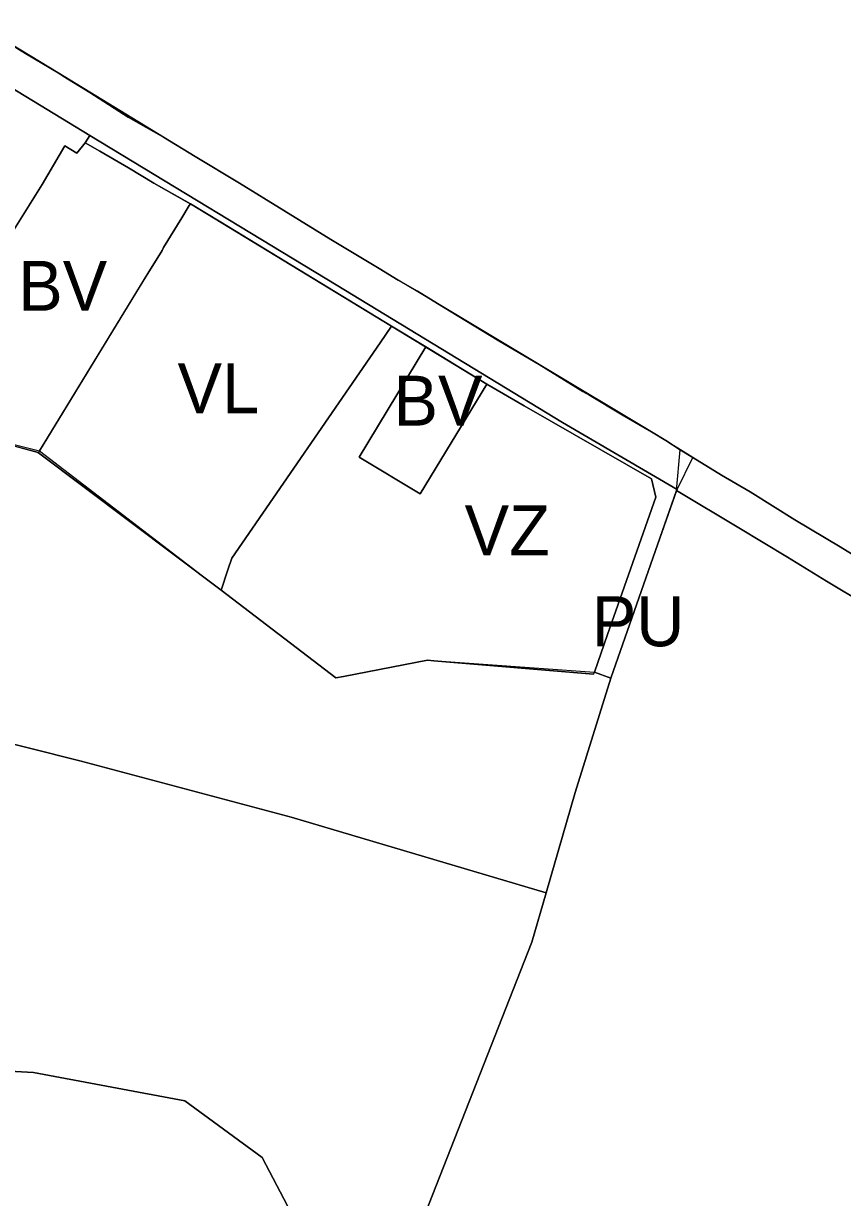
# Model space of a CAD drawing. Extents: x -555509 to -553005, y -1186756 to -1182560.
# Drawn here: x -553829.3 to -553599.5, y -1185808.2 to -1185478.8 of the extents above; entities that cross this region are included whole.
import ezdxf

# ---------------------------------------------------------------- set-up
doc = ezdxf.new("R2010")
doc.units = 0
for name, color, linetype in [('Level 15', 7, 'Continuous'), ('Level 36', 7, 'Continuous'), ('Level 52', 7, 'Continuous'), ('Level 59', 7, 'Continuous'), ('Level 6', 7, 'Continuous'), ('Level 63', 7, 'Continuous'), ('OBRYS_PLOCH', 7, 'Continuous'), ('stav_AL', 7, 'Continuous'), ('stav_AP', 7, 'Continuous'), ('stav_BV', 7, 'Continuous'), ('stav_DS', 7, 'Continuous'), ('stav_OS', 7, 'Continuous'), ('stav_PU', 7, 'Continuous'), ('stav_VL', 7, 'Continuous'), ('stav_VZ', 7, 'Continuous'), ('stav_ZK', 7, 'Continuous')]:
    doc.layers.add(name, color=color, linetype=linetype)

msp = doc.modelspace()

# ---------------------------------------------------------------- linework, layer by layer
at = {"layer": 'Level 15'}
for p, q in [((-553741.55, -1185552.19), (-553810.71, -1185510.27)), ((-553807.93, -1185514.67), (-553799.85, -1185519.34)), ((-553792.76, -1185523.64), (-553783.02, -1185529.12)), ((-553783.02, -1185529.12), (-553782.49, -1185529.43)), ((-553678.06, -1185590.77), (-553741.55, -1185552.19)), ((-553688.82, -1185586.12), (-553653.09, -1185606.6)), ((-553645.88, -1185609.63), (-553678.06, -1185590.77)), ((-553646.02, -1185609.88), (-553645.88, -1185609.63)), ((-553665.39, -1185650.28), (-553669.09, -1185660.85)), ((-553669.09, -1185660.85), (-553664.47, -1185662.51))]:
    msp.add_line(p, q, dxfattribs=at)
for points in [[(-553810.71, -1185510.27), (-553811.98, -1185512.28)], [(-553811.98, -1185512.28), (-553807.93, -1185514.67)], [(-553799.85, -1185519.34), (-553792.76, -1185523.64)], [(-553782.49, -1185529.43), (-553726.01, -1185563.76), (-553699.25, -1185580.02)], [(-553699.25, -1185580.02), (-553688.82, -1185586.12)], [(-553653.09, -1185606.6), (-553651.88, -1185611.74), (-553665.39, -1185650.28)], [(-553664.47, -1185662.51), (-553646.02, -1185609.88)]]:
    msp.add_lwpolyline(points, dxfattribs=at)
at = {"layer": 'Level 36'}
msp.add_lwpolyline([(-553842.47, -1185594.31), (-553824.8, -1185598.76), (-553773.82, -1185637.86), (-553741.7, -1185662.44), (-553715.92, -1185657.49), (-553669.09, -1185660.85), (-553664.47, -1185662.51), (-553645.88, -1185609.63), (-553641.45, -1185600.6), (-553653.09, -1185593.45), (-553684.56, -1185574.48), (-553713.17, -1185557.43), (-553724.17, -1185550.89), (-553743.1, -1185539.42), (-553756.23, -1185531.27), (-553768.7, -1185523.6), (-553781.13, -1185516.16), (-553790.01, -1185510.75), (-553819.6, -1185492.7), (-553841.14, -1185479.67)], dxfattribs=at)
at = {"layer": 'Level 52'}
for points in [[(-553669.37, -1185661.4), (-553669.09, -1185660.85), (-553664.47, -1185662.51), (-553646.02, -1185609.88), (-553645.05, -1185598.5), (-553649.07, -1185595.88), (-553653.09, -1185593.45), (-553661.34, -1185588.67), (-553670.5, -1185583.12), (-553672.3, -1185582.14), (-553684.56, -1185574.48), (-553695.87, -1185567.84), (-553707.58, -1185560.78), (-553713.17, -1185557.43), (-553718.78, -1185553.92), (-553724.17, -1185550.89), (-553729.53, -1185547.56), (-553736.09, -1185543.66), (-553743.1, -1185539.42), (-553756.23, -1185531.27), (-553768.7, -1185523.6), (-553781.13, -1185516.16), (-553790.01, -1185510.75), (-553799.92, -1185505.11), (-553810.66, -1185498.16), (-553818.19, -1185493.66), (-553819.6, -1185492.7), (-553828.72, -1185487.23), (-553841.14, -1185479.67)], [(-553840.96, -1185594.97), (-553825.6, -1185598.98), (-553825.09, -1185599.26), (-553773.82, -1185637.86), (-553741.7, -1185662.44), (-553739.47, -1185662.06), (-553715.92, -1185657.49), (-553714.12, -1185657.64), (-553669.37, -1185661.4)]]:
    msp.add_lwpolyline(points, dxfattribs=at)
at = {"layer": 'Level 6'}
for points in [[(-553669.37, -1185661.4), (-553669.09, -1185660.85), (-553664.47, -1185662.51), (-553646.02, -1185609.88), (-553645.05, -1185598.5), (-553649.07, -1185595.88), (-553653.09, -1185593.45), (-553661.34, -1185588.67), (-553670.5, -1185583.12), (-553672.3, -1185582.14), (-553684.56, -1185574.48), (-553695.87, -1185567.84), (-553707.58, -1185560.78), (-553713.17, -1185557.43), (-553718.78, -1185553.92), (-553724.17, -1185550.89), (-553729.53, -1185547.56), (-553736.09, -1185543.66), (-553743.1, -1185539.42), (-553756.23, -1185531.27), (-553768.7, -1185523.6), (-553781.13, -1185516.16), (-553790.01, -1185510.75), (-553799.92, -1185505.11), (-553810.66, -1185498.16), (-553818.19, -1185493.66), (-553819.6, -1185492.7), (-553828.72, -1185487.23), (-553841.14, -1185479.67)], [(-553840.96, -1185594.97), (-553825.6, -1185598.98), (-553825.09, -1185599.26), (-553773.82, -1185637.86), (-553741.7, -1185662.44), (-553739.47, -1185662.06), (-553715.92, -1185657.49), (-553714.12, -1185657.64), (-553669.37, -1185661.4)]]:
    msp.add_lwpolyline(points, dxfattribs=at)
at = {"layer": 'OBRYS_PLOCH'}
for p, q in [((-553810.71, -1185510.27), (-553811.98, -1185512.28)), ((-553741.55, -1185552.19), (-553810.71, -1185510.27)), ((-553810.71, -1185510.27), (-553741.55, -1185552.19)), ((-553811.98, -1185512.28), (-553807.93, -1185514.67)), ((-553807.93, -1185514.67), (-553811.98, -1185512.28)), ((-553807.93, -1185514.67), (-553799.85, -1185519.34)), ((-553799.85, -1185519.34), (-553807.93, -1185514.67)), ((-553768.7, -1185523.6), (-553781.13, -1185516.16)), ((-553799.85, -1185519.34), (-553792.76, -1185523.64)), ((-553792.76, -1185523.64), (-553799.85, -1185519.34)), ((-553792.76, -1185523.64), (-553783.02, -1185529.12)), ((-553782.49, -1185529.43), (-553792.76, -1185523.64)), ((-553782.81, -1185529.95), (-553784.83, -1185533.39)), ((-553784.83, -1185533.39), (-553782.81, -1185529.95)), ((-553783.02, -1185529.12), (-553782.49, -1185529.43)), ((-553782.49, -1185529.43), (-553782.81, -1185529.95)), ((-553782.81, -1185529.95), (-553782.49, -1185529.43)), ((-553773.94, -1185534.62), (-553782.49, -1185529.43)), ((-553784.83, -1185533.39), (-553789.98, -1185541.71)), ((-553726.01, -1185563.76), (-553773.94, -1185534.62)), ((-553789.98, -1185541.71), (-553790.41, -1185542.52)), ((-553736.09, -1185543.66), (-553743.1, -1185539.42)), ((-553790.41, -1185542.52), (-553794.42, -1185548.98)), ((-553729.53, -1185547.56), (-553736.09, -1185543.66)), ((-553724.17, -1185550.89), (-553729.53, -1185547.56)), ((-553795.51, -1185550.77), (-553824.8, -1185598.76)), ((-553794.42, -1185548.98), (-553795.51, -1185550.77)), ((-553718.78, -1185553.92), (-553724.17, -1185550.89)), ((-553678.06, -1185590.77), (-553741.55, -1185552.19)), ((-553741.55, -1185552.19), (-553678.06, -1185590.77)), ((-553713.17, -1185557.43), (-553718.78, -1185553.92)), ((-553707.58, -1185560.78), (-553713.17, -1185557.43)), ((-553729.23, -1185568.43), (-553726.01, -1185563.76)), ((-553770.83, -1185628.82), (-553729.23, -1185568.43)), ((-553716.43, -1185569.58), (-553735.08, -1185600.53)), ((-553699.25, -1185580.02), (-553716.43, -1185569.58)), ((-553672.3, -1185582.14), (-553684.56, -1185574.48)), ((-553699.25, -1185580.02), (-553688.82, -1185586.12)), ((-553670.5, -1185583.12), (-553672.3, -1185582.14)), ((-553661.34, -1185588.67), (-553670.5, -1185583.12)), ((-553653.09, -1185606.6), (-553688.82, -1185586.12)), ((-553688.82, -1185586.12), (-553653.09, -1185606.6)), ((-553645.88, -1185609.63), (-553678.06, -1185590.77)), ((-553678.06, -1185590.77), (-553645.88, -1185609.63)), ((-553645.05, -1185598.5), (-553649.07, -1185595.88)), ((-553824.8, -1185598.76), (-553825.09, -1185599.26)), ((-553825.09, -1185599.26), (-553773.82, -1185637.86)), ((-553641.45, -1185600.6), (-553645.05, -1185598.5)), ((-553664.47, -1185662.51), (-553646.02, -1185609.88)), ((-553646.02, -1185609.88), (-553664.47, -1185662.51)), ((-553646.02, -1185609.88), (-553664.47, -1185662.51)), ((-553646.02, -1185609.88), (-553645.88, -1185609.63)), ((-553645.88, -1185609.63), (-553646.02, -1185609.88)), ((-553646.02, -1185609.88), (-553628.57, -1185620.34)), ((-553628.57, -1185620.34), (-553646.02, -1185609.88)), ((-553628.57, -1185620.34), (-553646.02, -1185609.88)), ((-553628.57, -1185620.34), (-553614.92, -1185628.59)), ((-553614.92, -1185628.59), (-553628.57, -1185620.34)), ((-553614.92, -1185628.59), (-553628.57, -1185620.34)), ((-553771.93, -1185632.13), (-553770.83, -1185628.82)), ((-553603.99, -1185635.31), (-553614.92, -1185628.59)), ((-553773.82, -1185637.86), (-553771.93, -1185632.13)), ((-553592.98, -1185641.81), (-553603.99, -1185635.31)), ((-553665.39, -1185650.28), (-553669.09, -1185660.85)), ((-553715.92, -1185657.49), (-553739.47, -1185662.06)), ((-553674.53, -1185694.64), (-553664.47, -1185662.51)), ((-553664.47, -1185662.51), (-553674.53, -1185694.64)), ((-553664.47, -1185662.51), (-553674.53, -1185694.64)), ((-553664.47, -1185662.51), (-553669.09, -1185660.85)), ((-553669.09, -1185660.85), (-553664.47, -1185662.51)), ((-553754.19, -1185701.48), (-553813.14, -1185685.81)), ((-553674.53, -1185694.64), (-553682.62, -1185722.72)), ((-553674.53, -1185694.64), (-553682.62, -1185722.72)), ((-553682.62, -1185722.72), (-553754.19, -1185701.48)), ((-553682.62, -1185722.72), (-553686.62, -1185736.59)), ((-553682.62, -1185722.72), (-553686.62, -1185736.59)), ((-553686.62, -1185736.59), (-553682.62, -1185722.72)), ((-553686.62, -1185736.59), (-553735.32, -1185860.26)), ((-553686.62, -1185736.59), (-553735.32, -1185860.26)), ((-553735.32, -1185860.26), (-553686.62, -1185736.59)), ((-553826.51, -1185773.19), (-553784.01, -1185781.14))]:
    msp.add_line(p, q, dxfattribs=at)
for points in [[(-553811.98, -1185512.28), (-553810.71, -1185510.27), (-553822.69, -1185503.01), (-553895.23, -1185458.75), (-553919.14, -1185443.31)], [(-553895.23, -1185458.75), (-553822.69, -1185503.01), (-553810.71, -1185510.27)], [(-553841.14, -1185479.67), (-553828.72, -1185487.23), (-553819.6, -1185492.7), (-553818.19, -1185493.66), (-553810.66, -1185498.16), (-553799.92, -1185505.11), (-553790.01, -1185510.75), (-553781.13, -1185516.16), (-553768.7, -1185523.6), (-553756.23, -1185531.27), (-553743.1, -1185539.42)], [(-553781.13, -1185516.16), (-553790.01, -1185510.75), (-553799.92, -1185505.11), (-553810.66, -1185498.16), (-553818.19, -1185493.66), (-553819.6, -1185492.7), (-553828.72, -1185487.23), (-553841.14, -1185479.67)], [(-553811.98, -1185512.28), (-553814.34, -1185515.23), (-553817.72, -1185513.16), (-553824.1, -1185524.01), (-553862.7, -1185585.67)], [(-553853.58, -1185571.11), (-553824.1, -1185524.01), (-553817.72, -1185513.16), (-553814.34, -1185515.23), (-553811.98, -1185512.28)], [(-553743.1, -1185539.42), (-553756.23, -1185531.27), (-553768.7, -1185523.6)], [(-553782.49, -1185529.43), (-553726.01, -1185563.76), (-553699.25, -1185580.02)], [(-553822.54, -1185595.06), (-553794.42, -1185548.98), (-553790.41, -1185542.52), (-553789.98, -1185541.71), (-553784.83, -1185533.39)], [(-553743.1, -1185539.42), (-553736.09, -1185543.66), (-553729.53, -1185547.56), (-553724.17, -1185550.89), (-553718.78, -1185553.92), (-553713.17, -1185557.43), (-553707.58, -1185560.78), (-553695.87, -1185567.84), (-553684.56, -1185574.48)], [(-553684.56, -1185574.48), (-553695.87, -1185567.84), (-553707.58, -1185560.78)], [(-553688.82, -1185586.12), (-553699.25, -1185580.02), (-553718, -1185610.85), (-553735.08, -1185600.53), (-553716.43, -1185569.58), (-553726.01, -1185563.76), (-553729.23, -1185568.43), (-553770.83, -1185628.82)], [(-553684.56, -1185574.48), (-553672.3, -1185582.14), (-553670.5, -1185583.12), (-553661.34, -1185588.67), (-553653.09, -1185593.45), (-553649.07, -1185595.88), (-553645.05, -1185598.5), (-553641.45, -1185600.6), (-553633.44, -1185605.53), (-553625.4, -1185610.24), (-553612.83, -1185618.06), (-553600.11, -1185625.71), (-553587.43, -1185633.52)], [(-553735.08, -1185600.53), (-553718, -1185610.85), (-553699.25, -1185580.02)], [(-553649.07, -1185595.88), (-553653.09, -1185593.45), (-553661.34, -1185588.67)], [(-553842.47, -1185594.31), (-553840.96, -1185594.97), (-553825.6, -1185598.98), (-553825.09, -1185599.26)], [(-553773.82, -1185637.86), (-553825.09, -1185599.26), (-553840.96, -1185594.97)], [(-553825.09, -1185599.26), (-553824.8, -1185598.76), (-553822.54, -1185595.06)], [(-553625.4, -1185610.24), (-553633.44, -1185605.53), (-553641.45, -1185600.6)], [(-553665.39, -1185650.28), (-553651.88, -1185611.74), (-553653.09, -1185606.6)], [(-553653.09, -1185606.6), (-553651.88, -1185611.74), (-553665.39, -1185650.28)], [(-553587.43, -1185633.52), (-553600.11, -1185625.71), (-553612.83, -1185618.06), (-553625.4, -1185610.24)], [(-553770.83, -1185628.82), (-553771.93, -1185632.13), (-553773.82, -1185637.86), (-553741.7, -1185662.44), (-553739.47, -1185662.06), (-553715.92, -1185657.49), (-553714.12, -1185657.64), (-553669.37, -1185661.4), (-553669.09, -1185660.85), (-553665.39, -1185650.28)], [(-553614.92, -1185628.59), (-553603.99, -1185635.31), (-553592.98, -1185641.81)], [(-553591.54, -1185642.86), (-553592.98, -1185641.81), (-553603.99, -1185635.31), (-553614.92, -1185628.59)], [(-553739.47, -1185662.06), (-553741.7, -1185662.44), (-553773.82, -1185637.86)], [(-553669.09, -1185660.85), (-553669.37, -1185661.4), (-553714.12, -1185657.64), (-553715.92, -1185657.49)], [(-553753.81, -1185820.66), (-553753.12, -1185814.47), (-553762.29, -1185797.04), (-553784.01, -1185781.14), (-553826.51, -1185773.19), (-553905.75, -1185768.76), (-553885.33, -1185687.44), (-553881.88, -1185682.28), (-553877.28, -1185678.22), (-553871.61, -1185675.43), (-553866.15, -1185674.26), (-553858.58, -1185674.39), (-553813.14, -1185685.81), (-553754.19, -1185701.48), (-553682.62, -1185722.72), (-553674.53, -1185694.64)], [(-553871.61, -1185675.43), (-553877.28, -1185678.22), (-553881.88, -1185682.28), (-553885.33, -1185687.44), (-553905.75, -1185768.76), (-553826.51, -1185773.19)], [(-553813.14, -1185685.81), (-553858.58, -1185674.39), (-553866.15, -1185674.26)], [(-553784.01, -1185781.14), (-553762.29, -1185797.04), (-553753.12, -1185814.47)]]:
    msp.add_lwpolyline(points, dxfattribs=at)
at = {"layer": 'stav_AL'}
for p, q in [((-553686.62, -1185736.59), (-553682.62, -1185722.72)), ((-553735.32, -1185860.26), (-553686.62, -1185736.59))]:
    msp.add_line(p, q, dxfattribs=at)
msp.add_lwpolyline([(-553682.62, -1185722.72), (-553754.19, -1185701.48), (-553813.14, -1185685.81), (-553858.58, -1185674.39), (-553866.15, -1185674.26), (-553871.61, -1185675.43), (-553877.28, -1185678.22), (-553881.88, -1185682.28), (-553885.33, -1185687.44), (-553905.75, -1185768.76), (-553826.51, -1185773.19), (-553784.01, -1185781.14), (-553762.29, -1185797.04), (-553753.12, -1185814.47), (-553753.81, -1185820.66)], dxfattribs=at)
at = {"layer": 'stav_AP'}
for p, q in [((-553646.02, -1185609.88), (-553664.47, -1185662.51)), ((-553628.57, -1185620.34), (-553646.02, -1185609.88)), ((-553614.92, -1185628.59), (-553628.57, -1185620.34)), ((-553603.99, -1185635.31), (-553614.92, -1185628.59)), ((-553592.98, -1185641.81), (-553603.99, -1185635.31)), ((-553664.47, -1185662.51), (-553674.53, -1185694.64)), ((-553674.53, -1185694.64), (-553682.62, -1185722.72)), ((-553682.62, -1185722.72), (-553686.62, -1185736.59)), ((-553686.62, -1185736.59), (-553735.32, -1185860.26))]:
    msp.add_line(p, q, dxfattribs=at)
for points in [[(-553841.14, -1185479.67), (-553828.72, -1185487.23), (-553819.6, -1185492.7), (-553818.19, -1185493.66), (-553810.66, -1185498.16), (-553799.92, -1185505.11), (-553790.01, -1185510.75), (-553781.13, -1185516.16), (-553768.7, -1185523.6), (-553756.23, -1185531.27), (-553743.1, -1185539.42)], [(-553743.1, -1185539.42), (-553736.09, -1185543.66), (-553729.53, -1185547.56), (-553724.17, -1185550.89), (-553718.78, -1185553.92), (-553713.17, -1185557.43), (-553707.58, -1185560.78), (-553695.87, -1185567.84), (-553684.56, -1185574.48)], [(-553684.56, -1185574.48), (-553672.3, -1185582.14), (-553670.5, -1185583.12), (-553661.34, -1185588.67), (-553653.09, -1185593.45), (-553649.07, -1185595.88), (-553645.05, -1185598.5), (-553641.45, -1185600.6), (-553633.44, -1185605.53), (-553625.4, -1185610.24), (-553612.83, -1185618.06), (-553600.11, -1185625.71), (-553587.43, -1185633.52)]]:
    msp.add_lwpolyline(points, dxfattribs=at)
at = {"layer": 'stav_BV'}
for p, q in [((-553807.93, -1185514.67), (-553811.98, -1185512.28)), ((-553799.85, -1185519.34), (-553807.93, -1185514.67)), ((-553792.76, -1185523.64), (-553799.85, -1185519.34)), ((-553782.49, -1185529.43), (-553792.76, -1185523.64)), ((-553784.83, -1185533.39), (-553782.81, -1185529.95)), ((-553782.81, -1185529.95), (-553782.49, -1185529.43)), ((-553716.43, -1185569.58), (-553735.08, -1185600.53)), ((-553699.25, -1185580.02), (-553716.43, -1185569.58))]:
    msp.add_line(p, q, dxfattribs=at)
for points in [[(-553811.98, -1185512.28), (-553814.34, -1185515.23), (-553817.72, -1185513.16), (-553824.1, -1185524.01), (-553862.7, -1185585.67)], [(-553822.54, -1185595.06), (-553794.42, -1185548.98), (-553790.41, -1185542.52), (-553789.98, -1185541.71), (-553784.83, -1185533.39)], [(-553735.08, -1185600.53), (-553718, -1185610.85), (-553699.25, -1185580.02)], [(-553842.47, -1185594.31), (-553840.96, -1185594.97), (-553825.6, -1185598.98), (-553825.09, -1185599.26)], [(-553825.09, -1185599.26), (-553824.8, -1185598.76), (-553822.54, -1185595.06)]]:
    msp.add_lwpolyline(points, dxfattribs=at)
at = {"layer": 'stav_DS'}
for p, q in [((-553799.92, -1185505.11), (-553810.66, -1185498.16)), ((-553790.01, -1185510.75), (-553799.92, -1185505.11)), ((-553810.71, -1185510.27), (-553741.55, -1185552.19)), ((-553781.13, -1185516.16), (-553790.01, -1185510.75)), ((-553736.09, -1185543.66), (-553743.1, -1185539.42)), ((-553729.53, -1185547.56), (-553736.09, -1185543.66)), ((-553724.17, -1185550.89), (-553729.53, -1185547.56)), ((-553718.78, -1185553.92), (-553724.17, -1185550.89)), ((-553741.55, -1185552.19), (-553678.06, -1185590.77)), ((-553713.17, -1185557.43), (-553718.78, -1185553.92)), ((-553707.58, -1185560.78), (-553713.17, -1185557.43)), ((-553695.87, -1185567.84), (-553707.58, -1185560.78)), ((-553684.56, -1185574.48), (-553695.87, -1185567.84)), ((-553672.3, -1185582.14), (-553684.56, -1185574.48)), ((-553670.5, -1185583.12), (-553672.3, -1185582.14)), ((-553661.34, -1185588.67), (-553670.5, -1185583.12)), ((-553678.06, -1185590.77), (-553645.88, -1185609.63)), ((-553653.09, -1185593.45), (-553661.34, -1185588.67)), ((-553641.45, -1185600.6), (-553645.05, -1185598.5)), ((-553645.88, -1185609.63), (-553646.02, -1185609.88)), ((-553646.02, -1185609.88), (-553628.57, -1185620.34)), ((-553628.57, -1185620.34), (-553614.92, -1185628.59)), ((-553614.92, -1185628.59), (-553603.99, -1185635.31))]:
    msp.add_line(p, q, dxfattribs=at)
for points in [[(-553828.72, -1185487.23), (-553841.14, -1185479.67), (-553854.52, -1185471.56), (-553867.47, -1185463.68), (-553880.42, -1185455.64)], [(-553895.23, -1185458.75), (-553822.69, -1185503.01), (-553810.71, -1185510.27)], [(-553810.66, -1185498.16), (-553818.19, -1185493.66), (-553819.6, -1185492.7), (-553828.72, -1185487.23)], [(-553743.1, -1185539.42), (-553756.23, -1185531.27), (-553768.7, -1185523.6), (-553781.13, -1185516.16)], [(-553645.05, -1185598.5), (-553649.07, -1185595.88), (-553653.09, -1185593.45)], [(-553612.83, -1185618.06), (-553625.4, -1185610.24), (-553633.44, -1185605.53), (-553641.45, -1185600.6)], [(-553587.43, -1185633.52), (-553600.11, -1185625.71), (-553612.83, -1185618.06)], [(-553603.99, -1185635.31), (-553592.98, -1185641.81), (-553591.54, -1185642.86)]]:
    msp.add_lwpolyline(points, dxfattribs=at)
at = {"layer": 'stav_OS'}
for points in [[(-553811.98, -1185512.28), (-553810.71, -1185510.27), (-553822.69, -1185503.01), (-553895.23, -1185458.75), (-553919.14, -1185443.31)], [(-553853.58, -1185571.11), (-553824.1, -1185524.01), (-553817.72, -1185513.16), (-553814.34, -1185515.23), (-553811.98, -1185512.28)]]:
    msp.add_lwpolyline(points, dxfattribs=at)
at = {"layer": 'stav_PU'}
for p, q in [((-553810.71, -1185510.27), (-553811.98, -1185512.28)), ((-553741.55, -1185552.19), (-553810.71, -1185510.27)), ((-553811.98, -1185512.28), (-553807.93, -1185514.67)), ((-553807.93, -1185514.67), (-553799.85, -1185519.34)), ((-553799.85, -1185519.34), (-553792.76, -1185523.64)), ((-553792.76, -1185523.64), (-553783.02, -1185529.12)), ((-553783.02, -1185529.12), (-553782.49, -1185529.43)), ((-553678.06, -1185590.77), (-553741.55, -1185552.19)), ((-553699.25, -1185580.02), (-553688.82, -1185586.12)), ((-553688.82, -1185586.12), (-553653.09, -1185606.6)), ((-553645.88, -1185609.63), (-553678.06, -1185590.77)), ((-553664.47, -1185662.51), (-553646.02, -1185609.88)), ((-553646.02, -1185609.88), (-553645.88, -1185609.63)), ((-553665.39, -1185650.28), (-553669.09, -1185660.85)), ((-553669.09, -1185660.85), (-553664.47, -1185662.51))]:
    msp.add_line(p, q, dxfattribs=at)
for points in [[(-553782.49, -1185529.43), (-553726.01, -1185563.76), (-553699.25, -1185580.02)], [(-553653.09, -1185606.6), (-553651.88, -1185611.74), (-553665.39, -1185650.28)]]:
    msp.add_lwpolyline(points, dxfattribs=at)
at = {"layer": 'stav_VL'}
for p, q in [((-553782.81, -1185529.95), (-553784.83, -1185533.39)), ((-553782.49, -1185529.43), (-553782.81, -1185529.95)), ((-553773.94, -1185534.62), (-553782.49, -1185529.43)), ((-553784.83, -1185533.39), (-553789.98, -1185541.71)), ((-553726.01, -1185563.76), (-553773.94, -1185534.62)), ((-553789.98, -1185541.71), (-553790.41, -1185542.52)), ((-553790.41, -1185542.52), (-553794.42, -1185548.98)), ((-553795.51, -1185550.77), (-553824.8, -1185598.76)), ((-553794.42, -1185548.98), (-553795.51, -1185550.77)), ((-553729.23, -1185568.43), (-553726.01, -1185563.76)), ((-553770.83, -1185628.82), (-553729.23, -1185568.43)), ((-553824.8, -1185598.76), (-553825.09, -1185599.26)), ((-553825.09, -1185599.26), (-553773.82, -1185637.86)), ((-553771.93, -1185632.13), (-553770.83, -1185628.82)), ((-553773.82, -1185637.86), (-553771.93, -1185632.13))]:
    msp.add_line(p, q, dxfattribs=at)
at = {"layer": 'stav_VZ'}
msp.add_line((-553653.09, -1185606.6), (-553688.82, -1185586.12), dxfattribs=at)
for points in [[(-553688.82, -1185586.12), (-553699.25, -1185580.02), (-553718, -1185610.85), (-553735.08, -1185600.53), (-553716.43, -1185569.58), (-553726.01, -1185563.76), (-553729.23, -1185568.43), (-553770.83, -1185628.82)], [(-553665.39, -1185650.28), (-553651.88, -1185611.74), (-553653.09, -1185606.6)], [(-553770.83, -1185628.82), (-553771.93, -1185632.13), (-553773.82, -1185637.86), (-553741.7, -1185662.44), (-553739.47, -1185662.06), (-553715.92, -1185657.49), (-553714.12, -1185657.64), (-553669.37, -1185661.4), (-553669.09, -1185660.85), (-553665.39, -1185650.28)]]:
    msp.add_lwpolyline(points, dxfattribs=at)
at = {"layer": 'stav_ZK'}
for p, q in [((-553715.92, -1185657.49), (-553739.47, -1185662.06)), ((-553674.53, -1185694.64), (-553664.47, -1185662.51)), ((-553664.47, -1185662.51), (-553669.09, -1185660.85))]:
    msp.add_line(p, q, dxfattribs=at)
for points in [[(-553773.82, -1185637.86), (-553825.09, -1185599.26), (-553840.96, -1185594.97)], [(-553739.47, -1185662.06), (-553741.7, -1185662.44), (-553773.82, -1185637.86)], [(-553669.09, -1185660.85), (-553669.37, -1185661.4), (-553714.12, -1185657.64), (-553715.92, -1185657.49)], [(-553753.81, -1185820.66), (-553753.12, -1185814.47), (-553762.29, -1185797.04), (-553784.01, -1185781.14), (-553826.51, -1185773.19), (-553905.75, -1185768.76), (-553885.33, -1185687.44), (-553881.88, -1185682.28), (-553877.28, -1185678.22), (-553871.61, -1185675.43), (-553866.15, -1185674.26), (-553858.58, -1185674.39), (-553813.14, -1185685.81), (-553754.19, -1185701.48), (-553682.62, -1185722.72), (-553674.53, -1185694.64)]]:
    msp.add_lwpolyline(points, dxfattribs=at)

# ---------------------------------------------------------------- texts
at = {"layer": 'Level 59'}
for s, p in [('BV', (-553830.79, -1185559.44)), ('BV', (-553725.47, -1185591.66)), ('VZ', (-553705.51, -1185628.07)), ('PU', (-553669.84, -1185653.57))]:
    msp.add_text(s, height=14, dxfattribs=at).set_placement(p)
at = {"layer": 'Level 63'}
msp.add_text('VL', height=14, dxfattribs=at).set_placement((-553786.08, -1185588.19))

doc.saveas('drawing.dxf')
